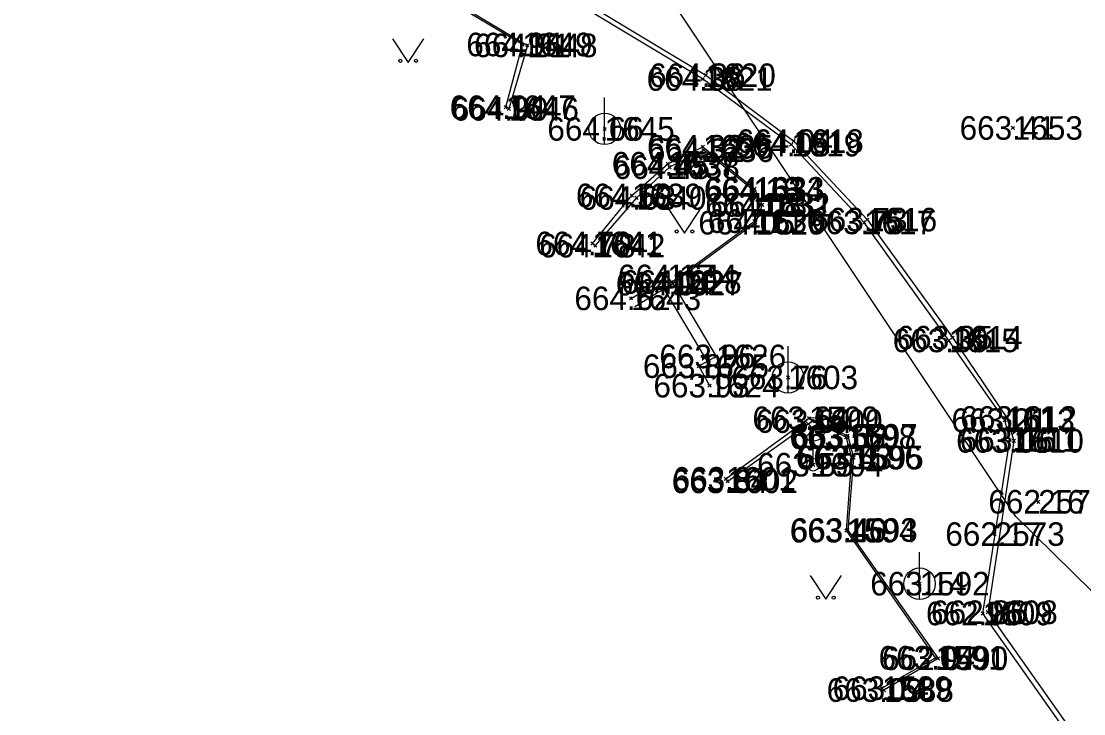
# Model space of a CAD drawing. Extents: x -844765 to -843273, y -997542 to -995529.
# Drawn here: x -844314.52 to -844280.68, y -996587.34 to -996565.28 of the extents above; entities that cross this region are included whole.
import ezdxf

# ---------------------------------------------------------------- set-up
doc = ezdxf.new("R2010")
doc.units = 0
for name, color, linetype in [('Benešův rám', 7, 'Continuous'), ('Betonový strop', 7, 'Continuous'), ('Dno', 7, 'Continuous'), ('Doplněk polohopisu', 7, 'Continuous'), ('Groma', 7, 'Continuous'), ('Osa', 7, 'Continuous'), ('Sítě podzemní nerozlišené', 7, 'Continuous'), ('Číslo bodu', 7, 'Continuous'), ('Řezy', 7, 'Continuous')]:
    doc.layers.add(name, color=color, linetype=linetype)

msp = doc.modelspace()

# ---------------------------------------------------------------- linework, layer by layer
at = {"layer": 'Benešův rám'}
for p, q in [((-844295.1, -996574.11), (-844293.95, -996573.41)), ((-844293.95, -996573.41), (-844293.81, -996573.59)), ((-844293.77, -996573.64), (-844294.98, -996574.376)), ((-844293.81, -996573.59), (-844293.77, -996573.64))]:
    msp.add_line(p, q, dxfattribs=at)
at = {"layer": 'Betonový strop'}
for points in [[(-844238.18, -996642.06), (-844239.24, -996647.29), (-844254.7, -996625.45), (-844265.09, -996610.79), (-844283.9, -996584.15), (-844283.04, -996578.62), (-844283.2, -996577.99), (-844284.98, -996575.45), (-844287.68, -996571.69), (-844290, -996569.21), (-844292.82, -996567.12), (-844302.54, -996561.26)], [(-844302.45, -996561.13), (-844292.72, -996567), (-844289.92, -996569.1), (-844287.58, -996571.6), (-844284.86, -996575.36), (-844283.13, -996577.92), (-844282.91, -996578.65), (-844283.74, -996584.11), (-844264.98, -996610.71), (-844254.61, -996625.37), (-844239.28, -996646.97), (-844238.31, -996642.04)], [(-844299.09, -996568.02), (-844298.56, -996566.02), (-844304.08, -996562.74)], [(-844304.04, -996562.68), (-844298.4, -996566.05), (-844298.99, -996568.07)], [(-844296.33, -996572.36), (-844295.07, -996570.83), (-844293.93, -996569.82), (-844292.81, -996569.28), (-844291.17, -996570.62), (-844290.92, -996571.13), (-844291.14, -996571.7), (-844293.77, -996573.64)], [(-844293.81, -996573.59), (-844291.17, -996571.65), (-844290.99, -996571.13), (-844291.21, -996570.66), (-844292.78, -996569.39), (-844293.87, -996569.93), (-844294.93, -996570.91), (-844296.24, -996572.43)], [(-844294.054, -996573.809), (-844292.678, -996576.122)], [(-844293.77, -996573.64), (-844292.39, -996575.96), (-844292.94, -996576.27), (-844292.6, -996576.89)], [(-844292.08, -996579.86), (-844289.43, -996577.93), (-844288.2, -996578.49), (-844288.01, -996579.18), (-844288.2, -996581.49), (-844285.32, -996585.58), (-844287.05, -996586.59)], [(-844287.11, -996586.53), (-844285.4, -996585.56), (-844288.24, -996581.51), (-844288.07, -996579.18), (-844288.25, -996578.53), (-844289.32, -996578.02), (-844292.02, -996579.94)]]:
    msp.add_lwpolyline(points, dxfattribs=at)
at = {"layer": 'Dno'}
for points in [[(-844302.696, -996565.84), (-844302.196, -996566.59), (-844301.696, -996565.84)], [(-844293.895, -996571.28), (-844293.395, -996572.03), (-844292.895, -996571.28)], [(-844289.396, -996582.943), (-844288.896, -996583.693), (-844288.396, -996582.943)]]:
    msp.add_lwpolyline(points, dxfattribs=at)
for centre in [(-844302.446, -996566.54), (-844301.946, -996566.54), (-844293.645, -996571.98), (-844293.145, -996571.98), (-844289.146, -996583.643), (-844288.646, -996583.643)]:
    msp.add_circle(centre, 0.05, dxfattribs=at)
at = {"layer": 'Doplněk polohopisu'}
for p, q in [((-844295.94, -996569.21), (-844295.94, -996567.71)), ((-844290.1, -996577.13), (-844290.1, -996575.63)), ((-844285.91, -996583.7), (-844285.91, -996582.2))]:
    msp.add_line(p, q, dxfattribs=at)
for centre in [(-844295.94, -996568.71), (-844290.1, -996576.63), (-844285.91, -996583.2)]:
    msp.add_circle(centre, 0.5, dxfattribs=at)
at = {"layer": 'Groma'}
for p, q in [((-844289.564, -996578.548), (-844289.036, -996578.02)), ((-844289.028, -996578.545), (-844289.556, -996578.016)), ((-844289.3, -996579.21), (-844289.3, -996578.66))]:
    msp.add_line(p, q, dxfattribs=at)
for centre, radius in [((-844289.3, -996578.285), 0.375), ((-844289.3, -996579.41), 0.2)]:
    msp.add_circle(centre, radius, dxfattribs=at)
at = {"layer": 'Osa'}
msp.add_lwpolyline([(-844256.985, -996614.3), (-844264.955, -996604.805), (-844272.513, -996594.138), (-844280.435, -996583.425), (-844282.85, -996581.055), (-844288.34, -996572.812), (-844293.83, -996564.57), (-844300.425, -996547.97), (-844303.975, -996538.71), (-844307.525, -996529.45), (-844315.28, -996511.19), (-844322.67, -996492.595), (-844328.875, -996473.55)], dxfattribs=at)
at = {"layer": 'Sítě podzemní nerozlišené'}
for p, q in [((-844298.56, -996566.02), (-844298.61, -996565.97)), ((-844298.56, -996566.02), (-844298.61, -996566.07)), ((-844298.56, -996566.02), (-844298.51, -996565.97)), ((-844298.56, -996566.02), (-844298.51, -996566.07)), ((-844298.4, -996566.05), (-844298.45, -996566)), ((-844298.4, -996566.05), (-844298.45, -996566.1)), ((-844298.4, -996566.05), (-844298.35, -996566)), ((-844298.4, -996566.05), (-844298.35, -996566.1)), ((-844292.82, -996567.12), (-844292.87, -996567.07)), ((-844292.82, -996567.12), (-844292.87, -996567.17)), ((-844292.82, -996567.12), (-844292.77, -996567.07)), ((-844292.82, -996567.12), (-844292.77, -996567.17)), ((-844292.72, -996567), (-844292.77, -996566.95)), ((-844292.72, -996567), (-844292.77, -996567.05)), ((-844292.72, -996567), (-844292.67, -996566.95)), ((-844292.72, -996567), (-844292.67, -996567.05)), ((-844299.09, -996568.02), (-844299.14, -996567.97)), ((-844299.09, -996568.02), (-844299.14, -996568.07)), ((-844299.09, -996568.02), (-844299.04, -996567.97)), ((-844299.09, -996568.02), (-844299.04, -996568.07)), ((-844298.99, -996568.07), (-844299.04, -996568.02)), ((-844298.99, -996568.07), (-844299.04, -996568.12)), ((-844298.99, -996568.07), (-844298.94, -996568.02)), ((-844298.99, -996568.07), (-844298.94, -996568.12)), ((-844295.94, -996568.71), (-844295.99, -996568.66)), ((-844295.94, -996568.71), (-844295.99, -996568.76)), ((-844295.94, -996568.71), (-844295.89, -996568.66)), ((-844295.94, -996568.71), (-844295.89, -996568.76)), ((-844282.94, -996568.68), (-844282.99, -996568.63)), ((-844282.94, -996568.68), (-844282.99, -996568.73)), ((-844282.94, -996568.68), (-844282.89, -996568.63)), ((-844282.94, -996568.68), (-844282.89, -996568.73)), ((-844290, -996569.21), (-844290.05, -996569.16)), ((-844290, -996569.21), (-844289.95, -996569.16)), ((-844289.92, -996569.1), (-844289.97, -996569.05)), ((-844289.92, -996569.1), (-844289.97, -996569.15)), ((-844289.92, -996569.1), (-844289.87, -996569.05)), ((-844289.92, -996569.1), (-844289.87, -996569.15)), ((-844292.81, -996569.28), (-844292.86, -996569.23)), ((-844292.81, -996569.28), (-844292.86, -996569.33)), ((-844292.78, -996569.39), (-844292.83, -996569.34)), ((-844292.78, -996569.39), (-844292.83, -996569.44)), ((-844292.81, -996569.28), (-844292.76, -996569.23)), ((-844292.81, -996569.28), (-844292.76, -996569.33)), ((-844292.78, -996569.39), (-844292.73, -996569.34)), ((-844292.78, -996569.39), (-844292.73, -996569.44)), ((-844290, -996569.21), (-844290.05, -996569.26)), ((-844290, -996569.21), (-844289.95, -996569.26)), ((-844293.93, -996569.82), (-844293.98, -996569.77)), ((-844293.93, -996569.82), (-844293.98, -996569.87)), ((-844293.93, -996569.82), (-844293.88, -996569.77)), ((-844293.93, -996569.82), (-844293.88, -996569.87)), ((-844293.87, -996569.93), (-844293.92, -996569.88)), ((-844293.87, -996569.93), (-844293.92, -996569.98)), ((-844293.87, -996569.93), (-844293.82, -996569.88)), ((-844293.87, -996569.93), (-844293.82, -996569.98)), ((-844295.07, -996570.83), (-844295.12, -996570.78)), ((-844295.07, -996570.83), (-844295.12, -996570.88)), ((-844295.07, -996570.83), (-844295.02, -996570.78)), ((-844295.07, -996570.83), (-844295.02, -996570.88)), ((-844294.93, -996570.91), (-844294.98, -996570.86)), ((-844294.93, -996570.91), (-844294.88, -996570.86)), ((-844291.21, -996570.66), (-844291.26, -996570.61)), ((-844291.21, -996570.66), (-844291.26, -996570.71)), ((-844291.17, -996570.62), (-844291.22, -996570.57)), ((-844291.17, -996570.62), (-844291.22, -996570.67)), ((-844291.21, -996570.66), (-844291.16, -996570.61)), ((-844291.21, -996570.66), (-844291.16, -996570.71)), ((-844291.17, -996570.62), (-844291.12, -996570.57)), ((-844291.17, -996570.62), (-844291.12, -996570.67)), ((-844294.93, -996570.91), (-844294.98, -996570.96)), ((-844294.93, -996570.91), (-844294.88, -996570.96)), ((-844290.99, -996571.13), (-844291.04, -996571.08)), ((-844290.99, -996571.13), (-844291.04, -996571.18)), ((-844290.99, -996571.13), (-844290.94, -996571.08)), ((-844290.99, -996571.13), (-844290.94, -996571.18)), ((-844290.92, -996571.13), (-844290.97, -996571.08)), ((-844290.92, -996571.13), (-844290.97, -996571.18)), ((-844290.92, -996571.13), (-844290.87, -996571.08)), ((-844290.92, -996571.13), (-844290.87, -996571.18)), ((-844287.58, -996571.6), (-844287.63, -996571.55)), ((-844287.58, -996571.6), (-844287.53, -996571.55)), ((-844291.17, -996571.65), (-844291.22, -996571.6)), ((-844291.17, -996571.65), (-844291.22, -996571.7)), ((-844291.14, -996571.7), (-844291.19, -996571.65)), ((-844291.14, -996571.7), (-844291.19, -996571.75)), ((-844291.17, -996571.65), (-844291.12, -996571.6)), ((-844291.17, -996571.65), (-844291.12, -996571.7)), ((-844291.14, -996571.7), (-844291.09, -996571.65)), ((-844291.14, -996571.7), (-844291.09, -996571.75)), ((-844287.68, -996571.69), (-844287.73, -996571.64)), ((-844287.68, -996571.69), (-844287.73, -996571.74)), ((-844287.68, -996571.69), (-844287.63, -996571.64)), ((-844287.68, -996571.69), (-844287.63, -996571.74)), ((-844287.58, -996571.6), (-844287.63, -996571.65)), ((-844287.58, -996571.6), (-844287.53, -996571.65)), ((-844296.33, -996572.36), (-844296.38, -996572.31)), ((-844296.33, -996572.36), (-844296.38, -996572.41)), ((-844296.33, -996572.36), (-844296.28, -996572.31)), ((-844296.33, -996572.36), (-844296.28, -996572.41)), ((-844296.24, -996572.43), (-844296.29, -996572.38)), ((-844296.24, -996572.43), (-844296.29, -996572.48)), ((-844296.24, -996572.43), (-844296.19, -996572.38)), ((-844296.24, -996572.43), (-844296.19, -996572.48)), ((-844293.95, -996573.41), (-844294, -996573.36)), ((-844293.95, -996573.41), (-844294, -996573.46)), ((-844293.95, -996573.41), (-844293.9, -996573.36)), ((-844293.95, -996573.41), (-844293.9, -996573.46)), ((-844293.81, -996573.59), (-844293.86, -996573.54)), ((-844293.81, -996573.59), (-844293.76, -996573.54)), ((-844293.81, -996573.59), (-844293.86, -996573.64)), ((-844293.77, -996573.64), (-844293.82, -996573.59)), ((-844293.77, -996573.64), (-844293.82, -996573.69)), ((-844293.81, -996573.59), (-844293.76, -996573.64)), ((-844293.77, -996573.64), (-844293.72, -996573.59)), ((-844293.77, -996573.64), (-844293.72, -996573.69)), ((-844295.1, -996574.11), (-844295.15, -996574.06)), ((-844295.1, -996574.11), (-844295.15, -996574.16)), ((-844295.1, -996574.11), (-844295.05, -996574.06)), ((-844295.1, -996574.11), (-844295.05, -996574.16)), ((-844284.98, -996575.45), (-844285.03, -996575.4)), ((-844284.98, -996575.45), (-844285.03, -996575.5)), ((-844284.98, -996575.45), (-844284.93, -996575.4)), ((-844284.98, -996575.45), (-844284.93, -996575.5)), ((-844284.86, -996575.36), (-844284.91, -996575.31)), ((-844284.86, -996575.36), (-844284.91, -996575.41)), ((-844284.86, -996575.36), (-844284.81, -996575.31)), ((-844284.86, -996575.36), (-844284.81, -996575.41)), ((-844292.39, -996575.96), (-844292.44, -996575.91)), ((-844292.39, -996575.96), (-844292.34, -996575.91)), ((-844292.94, -996576.27), (-844292.99, -996576.22)), ((-844292.94, -996576.27), (-844292.99, -996576.32)), ((-844292.94, -996576.27), (-844292.89, -996576.22)), ((-844292.94, -996576.27), (-844292.89, -996576.32)), ((-844292.39, -996575.96), (-844292.44, -996576.01)), ((-844292.39, -996575.96), (-844292.34, -996576.01)), ((-844290.1, -996576.63), (-844290.15, -996576.58)), ((-844290.1, -996576.63), (-844290.05, -996576.58)), ((-844292.6, -996576.89), (-844292.65, -996576.84)), ((-844292.6, -996576.89), (-844292.65, -996576.94)), ((-844292.6, -996576.89), (-844292.55, -996576.84)), ((-844292.6, -996576.89), (-844292.55, -996576.94)), ((-844290.1, -996576.63), (-844290.15, -996576.68)), ((-844290.1, -996576.63), (-844290.05, -996576.68)), ((-844289.43, -996577.93), (-844289.48, -996577.88)), ((-844289.43, -996577.93), (-844289.48, -996577.98)), ((-844289.43, -996577.93), (-844289.38, -996577.88)), ((-844289.43, -996577.93), (-844289.38, -996577.98)), ((-844289.32, -996578.02), (-844289.37, -996577.97)), ((-844289.32, -996578.02), (-844289.27, -996577.97)), ((-844283.2, -996577.99), (-844283.25, -996577.94)), ((-844283.2, -996577.99), (-844283.15, -996577.94)), ((-844283.13, -996577.92), (-844283.18, -996577.87)), ((-844283.13, -996577.92), (-844283.18, -996577.97)), ((-844283.13, -996577.92), (-844283.08, -996577.87)), ((-844283.13, -996577.92), (-844283.08, -996577.97)), ((-844289.32, -996578.02), (-844289.37, -996578.07)), ((-844289.32, -996578.02), (-844289.27, -996578.07)), ((-844283.2, -996577.99), (-844283.25, -996578.04)), ((-844283.2, -996577.99), (-844283.15, -996578.04)), ((-844288.25, -996578.53), (-844288.3, -996578.48)), ((-844288.25, -996578.53), (-844288.3, -996578.58)), ((-844288.2, -996578.49), (-844288.25, -996578.44)), ((-844288.25, -996578.53), (-844288.2, -996578.48)), ((-844288.2, -996578.49), (-844288.25, -996578.54)), ((-844288.25, -996578.53), (-844288.2, -996578.58)), ((-844288.2, -996578.49), (-844288.15, -996578.44)), ((-844288.2, -996578.49), (-844288.15, -996578.54)), ((-844283.04, -996578.62), (-844283.09, -996578.57)), ((-844283.04, -996578.62), (-844283.09, -996578.67)), ((-844283.04, -996578.62), (-844282.99, -996578.57)), ((-844283.04, -996578.62), (-844282.99, -996578.67)), ((-844282.91, -996578.65), (-844282.96, -996578.6)), ((-844282.91, -996578.65), (-844282.96, -996578.7)), ((-844282.91, -996578.65), (-844282.86, -996578.6)), ((-844282.91, -996578.65), (-844282.86, -996578.7)), ((-844288.07, -996579.18), (-844288.12, -996579.13)), ((-844288.07, -996579.18), (-844288.12, -996579.23)), ((-844288.07, -996579.18), (-844288.02, -996579.13)), ((-844288.07, -996579.18), (-844288.02, -996579.23)), ((-844288.01, -996579.18), (-844288.06, -996579.13)), ((-844288.01, -996579.18), (-844288.06, -996579.23)), ((-844288.01, -996579.18), (-844287.96, -996579.13)), ((-844288.01, -996579.18), (-844287.96, -996579.23)), ((-844289.3, -996579.41), (-844289.35, -996579.36)), ((-844289.3, -996579.41), (-844289.35, -996579.46)), ((-844289.3, -996579.41), (-844289.25, -996579.36)), ((-844289.3, -996579.41), (-844289.25, -996579.46)), ((-844292.08, -996579.86), (-844292.13, -996579.81)), ((-844292.08, -996579.86), (-844292.13, -996579.91)), ((-844292.08, -996579.86), (-844292.03, -996579.81)), ((-844292.08, -996579.86), (-844292.03, -996579.91)), ((-844292.02, -996579.94), (-844292.07, -996579.89)), ((-844292.02, -996579.94), (-844292.07, -996579.99)), ((-844292.02, -996579.94), (-844291.97, -996579.89)), ((-844292.02, -996579.94), (-844291.97, -996579.99)), ((-844282.13, -996580.59), (-844282.18, -996580.54)), ((-844282.13, -996580.59), (-844282.18, -996580.64)), ((-844282.13, -996580.59), (-844282.08, -996580.54)), ((-844282.13, -996580.59), (-844282.08, -996580.64)), ((-844288.24, -996581.51), (-844288.29, -996581.46)), ((-844288.24, -996581.51), (-844288.29, -996581.56)), ((-844288.2, -996581.49), (-844288.25, -996581.44)), ((-844288.2, -996581.49), (-844288.25, -996581.54)), ((-844288.24, -996581.51), (-844288.19, -996581.46)), ((-844288.24, -996581.51), (-844288.19, -996581.56)), ((-844288.2, -996581.49), (-844288.15, -996581.44)), ((-844288.2, -996581.49), (-844288.15, -996581.54)), ((-844283.52, -996581.62), (-844283.57, -996581.57)), ((-844283.52, -996581.62), (-844283.57, -996581.67)), ((-844283.52, -996581.62), (-844283.47, -996581.57)), ((-844283.52, -996581.62), (-844283.47, -996581.67)), ((-844285.91, -996583.2), (-844285.96, -996583.15)), ((-844285.91, -996583.2), (-844285.96, -996583.25)), ((-844285.91, -996583.2), (-844285.86, -996583.15)), ((-844285.91, -996583.2), (-844285.86, -996583.25)), ((-844283.74, -996584.11), (-844283.79, -996584.06)), ((-844283.74, -996584.11), (-844283.69, -996584.06)), ((-844283.9, -996584.15), (-844283.95, -996584.1)), ((-844283.9, -996584.15), (-844283.95, -996584.2)), ((-844283.9, -996584.15), (-844283.85, -996584.1)), ((-844283.9, -996584.15), (-844283.85, -996584.2)), ((-844283.74, -996584.11), (-844283.79, -996584.16)), ((-844283.74, -996584.11), (-844283.69, -996584.16)), ((-844285.4, -996585.56), (-844285.45, -996585.51)), ((-844285.4, -996585.56), (-844285.45, -996585.61)), ((-844285.4, -996585.56), (-844285.35, -996585.51)), ((-844285.4, -996585.56), (-844285.35, -996585.61)), ((-844285.32, -996585.58), (-844285.37, -996585.53)), ((-844285.32, -996585.58), (-844285.37, -996585.63)), ((-844285.32, -996585.58), (-844285.27, -996585.53)), ((-844285.32, -996585.58), (-844285.27, -996585.63)), ((-844287.11, -996586.53), (-844287.16, -996586.48)), ((-844287.11, -996586.53), (-844287.16, -996586.58)), ((-844287.11, -996586.53), (-844287.06, -996586.48)), ((-844287.11, -996586.53), (-844287.06, -996586.58)), ((-844287.05, -996586.59), (-844287.1, -996586.54)), ((-844287.05, -996586.59), (-844287.1, -996586.64)), ((-844287.05, -996586.59), (-844287, -996586.54)), ((-844287.05, -996586.59), (-844287, -996586.64))]:
    msp.add_line(p, q, dxfattribs=at)

# ---------------------------------------------------------------- texts
at = {"layer": 'Číslo bodu'}
for s, p in [('1649', (-844298.56, -996566.395)), ('1648', (-844298.4, -996566.425)), ('1621', (-844292.82, -996567.495)), ('1620', (-844292.72, -996567.375)), ('1647', (-844299.09, -996568.395)), ('1646', (-844298.99, -996568.445)), ('1645', (-844295.94, -996569.085)), ('1653', (-844282.94, -996569.055)), ('1619', (-844290, -996569.585)), ('1618', (-844289.92, -996569.475)), ('1635', (-844292.81, -996569.655)), ('1636', (-844292.78, -996569.765)), ('1637', (-844293.93, -996570.195)), ('1638', (-844293.87, -996570.305)), ('1639', (-844295.07, -996571.205)), ('1640', (-844294.93, -996571.285)), ('1634', (-844291.21, -996571.035)), ('1633', (-844291.17, -996570.995)), ('1632', (-844290.99, -996571.505)), ('1631', (-844290.92, -996571.505)), ('1630', (-844291.17, -996572.025)), ('1629', (-844291.14, -996572.075)), ('1617', (-844287.68, -996572.065)), ('1616', (-844287.58, -996571.975)), ('1641', (-844296.33, -996572.735)), ('1642', (-844296.24, -996572.805)), ('1644', (-844293.95, -996573.785)), ('1628', (-844293.81, -996573.965)), ('1627', (-844293.77, -996574.015)), ('1643', (-844295.1, -996574.485)), ('1615', (-844284.98, -996575.825)), ('1614', (-844284.86, -996575.735)), ('1626', (-844292.39, -996576.335)), ('1625', (-844292.94, -996576.645)), ('1603', (-844290.1, -996577.005)), ('1624', (-844292.6, -996577.265)), ('1599', (-844289.43, -996578.305)), ('1600', (-844289.32, -996578.395)), ('1613', (-844283.2, -996578.365)), ('1612', (-844283.13, -996578.295)), ('1598', (-844288.25, -996578.905)), ('1597', (-844288.2, -996578.865)), ('1611', (-844283.04, -996578.995)), ('1610', (-844282.91, -996579.025)), ('1596', (-844288.07, -996579.555)), ('1595', (-844288.01, -996579.555)), ('1604', (-844289.3, -996579.785)), ('1601', (-844292.08, -996580.235)), ('1602', (-844292.02, -996580.315)), ('2574', (-844282.13, -996580.965)), ('1594', (-844288.24, -996581.885)), ('1593', (-844288.2, -996581.865)), ('2573', (-844283.52, -996581.995)), ('1592', (-844285.91, -996583.575)), ('1608', (-844283.74, -996584.485)), ('1609', (-844283.9, -996584.525)), ('1591', (-844285.4, -996585.935)), ('1590', (-844285.32, -996585.955)), ('1589', (-844287.11, -996586.905)), ('1588', (-844287.05, -996586.965))]:
    msp.add_text(s, height=0.75, dxfattribs=at).set_placement(p)
at = {"layer": 'Řezy'}
for s, p in [('664.94', (-844300.346, -996566.395)), ('664.91', (-844300.098, -996566.425)), ('664.38', (-844294.603, -996567.495)), ('664.36', (-844294.524, -996567.375)), ('664.94', (-844300.876, -996568.395)), ('664.90', (-844300.809, -996568.445)), ('664.66', (-844297.765, -996569.085)), ('663.41', (-844284.635, -996569.055)), ('664.05', (-844291.816, -996569.585)), ('664.04', (-844291.736, -996569.475)), ('664.32', (-844294.593, -996569.655)), ('664.32', (-844294.563, -996569.765)), ('664.45', (-844295.713, -996570.195)), ('664.45', (-844295.653, -996570.305)), ('664.59', (-844296.856, -996571.205)), ('664.63', (-844296.734, -996571.285)), ('664.18', (-844292.781, -996571.035)), ('664.13', (-844292.741, -996570.995)), ('664.08', (-844292.736, -996571.505)), ('664.13', (-844292.561, -996571.505)), ('664.05', (-844292.956, -996572.075)), ('664.11', (-844292.652, -996572.025)), ('663.75', (-844289.463, -996572.065)), ('663.73', (-844289.363, -996571.975)), ('664.70', (-844298.146, -996572.735)), ('664.78', (-844298.023, -996572.805)), ('664.17', (-844295.521, -996573.785)), ('664.10', (-844295.413, -996573.965)), ('664.04', (-844295.586, -996574.015)), ('664.62', (-844296.904, -996574.485)), ('663.39', (-844286.766, -996575.825)), ('663.35', (-844286.643, -996575.735)), ('663.96', (-844294.197, -996576.335)), ('663.87', (-844294.723, -996576.645)), ('663.76', (-844291.904, -996577.005)), ('663.93', (-844294.386, -996577.265)), ('663.64', (-844291.234, -996578.305)), ('663.64', (-844291.124, -996578.395)), ('663.21', (-844284.895, -996578.365)), ('663.11', (-844284.612, -996578.295)), ('663.56', (-844290.054, -996578.905)), ('663.52', (-844289.983, -996578.865)), ('663.06', (-844284.746, -996579.025)), ('663.16', (-844284.631, -996578.995)), ('663.53', (-844289.853, -996579.555)), ('663.47', (-844289.793, -996579.555)), ('663.55', (-844291.083, -996579.785)), ('663.84', (-844293.803, -996580.315)), ('663.81', (-844293.775, -996580.235)), ('662.16', (-844283.721, -996580.965)), ('663.46', (-844290.044, -996581.885)), ('663.40', (-844290.016, -996581.865)), ('662.17', (-844285.091, -996581.995)), ('663.14', (-844287.481, -996583.575)), ('662.86', (-844285.544, -996584.485)), ('662.96', (-844285.707, -996584.525)), ('663.04', (-844287.216, -996585.935)), ('662.97', (-844287.106, -996585.955)), ('663.09', (-844288.869, -996586.965)), ('663.14', (-844288.681, -996586.905))]:
    msp.add_text(s, height=0.75, dxfattribs=at).set_placement(p)

doc.saveas('drawing.dxf')
